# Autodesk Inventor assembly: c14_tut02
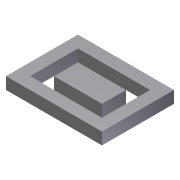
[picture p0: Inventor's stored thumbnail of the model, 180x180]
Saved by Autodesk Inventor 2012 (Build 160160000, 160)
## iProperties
Created: 2010-04
Part Number: c14_tut02
Document SubType Name: Assembly
Designer: CADSoft
Author: CADSoft
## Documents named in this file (3)
- C:\Users\CadCim\Documents\SAILESH\inventor-2011-fact-prt\c14-inv-2011-prt\c14_inv_2012_prt\Tutorial\c14_tut02.iam
- C:\Users\CadCim\Documents\SAILESH\inventor-2011-fact-prt\c14-inv-2011-prt\Tutorials\c14-tut02-inv\Outer Plate.ipt
- C:\Users\CadCim\Documents\SAILESH\inventor-2011-fact-prt\c14-inv-2011-prt\Tutorials\c14-tut02-inv\Inner Plate.ipt
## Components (2 placed, 2 different names)
1. Outer Plate:1 — Flush:1, Flush:2, Mate:1, Mate:2, Mate:3, Mate:4
2. Inner Plate:1 — Flush:1, Flush:2, Mate:1, Mate:2, Mate:3, Mate:4
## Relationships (6: Mate 4, Flush 2)
- Flush:1: Outer Plate:1 ↔ Inner Plate:1
- Flush:2: Outer Plate:1 ↔ Inner Plate:1
- Mate:1: Outer Plate:1 ↔ Inner Plate:1
- Mate:2: Outer Plate:1 ↔ Inner Plate:1
- Mate:3: Outer Plate:1 ↔ Inner Plate:1
- Mate:4: Outer Plate:1 ↔ Inner Plate:1
